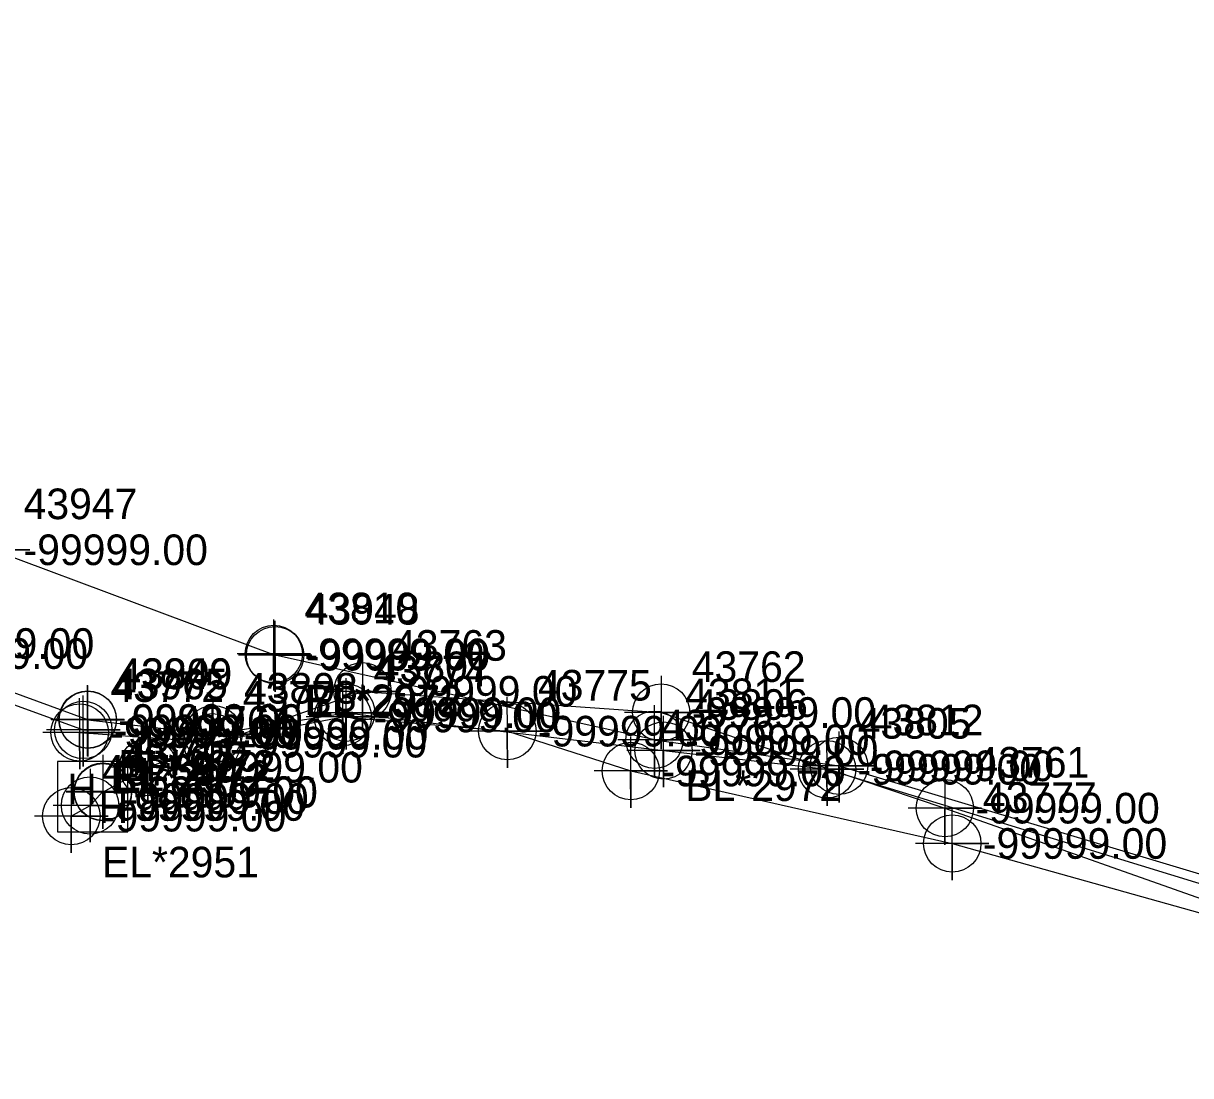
# Model space of a CAD drawing. Extents: x 2083698 to 2094313, y 743246 to 752873.
# Drawn here: x 2091439.4 to 2091534.7, y 747273.4 to 747359.3 of the extents above; entities that cross this region are included whole.
import ezdxf

# ---------------------------------------------------------------- set-up
doc = ezdxf.new("R2010")
doc.units = 0
for name, color, linetype in [('COGO Default Spiral', 7, 'Continuous'), ('Exist Other Culture Fence Line', 7, 'Continuous'), ('Exist Property Iron Pin Leader', 7, 'Continuous'), ('Exist Property Iron Pin Text', 7, 'Continuous'), ('Exist Property Monument Leader', 7, 'Continuous'), ('Exist Property Monument Text', 7, 'Continuous'), ('Exist Right of Way Line Leader', 7, 'Continuous'), ('Exist Right of Way Line Text', 7, 'Continuous'), ('Exist Utilities Power Joint Use Telephone Cogo Elevation', 7, 'Continuous'), ('Exist Utilities Power Joint Use Telephone Cogo Number', 7, 'Continuous'), ('Exist Utilities Power UG Cable SUE LOS B', 7, 'Continuous'), ('Exist Utilities Telephone UG Conduit SUE LOS B', 7, 'Continuous'), ('Scratch_Level_2', 7, 'Continuous'), ('Scratch_Level_3', 7, 'Continuous'), ('Scratch_Level_5', 7, 'Continuous')]:
    doc.layers.add(name, color=color, linetype=linetype)

msp = doc.modelspace()

# ---------------------------------------------------------------- linework, layer by layer
at = {"layer": 'COGO Default Spiral'}
msp.add_line((2091445.134, 747296.025), (2091445.134, 747296.025), dxfattribs=at)
msp.add_lwpolyline([(2091442.184, 747293.3), (2091447.934, 747293.3), (2091447.934, 747299.05), (2091442.184, 747299.05), (2091442.184, 747293.3)], dxfattribs=at)
at = {"layer": 'Exist Property Iron Pin Text'}
for points in [[(2091467.087, 747307.78), (2091467.087, 747301.78), (2091467.087, 747304.78), (2091470.087, 747304.78), (2091464.087, 747304.78)], [(2091491.485, 747306.049), (2091491.485, 747300.049), (2091491.485, 747303.049), (2091494.485, 747303.049), (2091488.485, 747303.049)], [(2091449.563, 747301.581), (2091449.563, 747295.581), (2091449.563, 747298.581), (2091452.563, 747298.581), (2091446.563, 747298.581)], [(2091445.88, 747299.588), (2091445.88, 747293.588), (2091445.88, 747296.588), (2091448.88, 747296.588), (2091442.88, 747296.588)], [(2091445.887, 747299.543), (2091445.887, 747293.543), (2091445.887, 747296.543), (2091448.887, 747296.543), (2091442.887, 747296.543)], [(2091444.836, 747298.46), (2091444.836, 747292.46), (2091444.836, 747295.46), (2091447.836, 747295.46), (2091441.836, 747295.46)], [(2091514.66, 747298.24), (2091514.66, 747292.24), (2091514.66, 747295.24), (2091517.66, 747295.24), (2091511.66, 747295.24)], [(2091443.305, 747297.587), (2091443.305, 747291.587), (2091443.305, 747294.587), (2091446.305, 747294.587), (2091440.305, 747294.587)]]:
    msp.add_lwpolyline(points, dxfattribs=at)
for centre in [(2091467.087, 747304.78), (2091491.485, 747303.049), (2091449.563, 747298.581), (2091445.88, 747296.588), (2091445.887, 747296.543), (2091444.836, 747295.46), (2091514.66, 747295.24), (2091443.305, 747294.587)]:
    msp.add_circle(centre, 2.344, dxfattribs=at)
at = {"layer": 'Exist Right of Way Line Text'}
for points in [[(2091436.874, 747319.158), (2091436.907, 747313.343), (2091436.89, 747316.343), (2091439.907, 747316.343), (2091433.907, 747316.343)], [(2091459.814, 747310.653), (2091459.847, 747304.838), (2091459.83, 747307.838), (2091462.847, 747307.838), (2091456.847, 747307.838)], [(2091459.918, 747310.548), (2091459.951, 747304.733), (2091459.934, 747307.733), (2091462.951, 747307.733), (2091456.951, 747307.733)], [(2091465.725, 747305.846), (2091465.758, 747300.031), (2091465.741, 747303.031), (2091468.758, 747303.031), (2091462.758, 747303.031)], [(2091444.601, 747305.295), (2091444.634, 747299.48), (2091444.617, 747302.48), (2091447.634, 747302.48), (2091441.634, 747302.48)], [(2091444.621, 747305.266), (2091444.654, 747299.451), (2091444.637, 747302.451), (2091447.654, 747302.451), (2091441.654, 747302.451)], [(2091465.448, 747305.502), (2091465.481, 747299.687), (2091465.464, 747302.687), (2091468.481, 747302.687), (2091462.481, 747302.687)], [(2091443.957, 747304.233), (2091443.99, 747298.418), (2091443.973, 747301.418), (2091446.99, 747301.418), (2091440.99, 747301.418)], [(2091444.251, 747304.444), (2091444.284, 747298.629), (2091444.267, 747301.629), (2091447.284, 747301.629), (2091441.284, 747301.629)], [(2091454.873, 747304.095), (2091454.906, 747298.28), (2091454.889, 747301.28), (2091457.906, 747301.28), (2091451.906, 747301.28)], [(2091478.888, 747304.344), (2091478.921, 747298.529), (2091478.904, 747301.529), (2091481.921, 747301.529), (2091475.921, 747301.529)], [(2091490.912, 747303.64), (2091490.945, 747297.825), (2091490.928, 747300.825), (2091493.945, 747300.825), (2091487.945, 747300.825)], [(2091454.781, 747303.444), (2091454.814, 747297.629), (2091454.797, 747300.629), (2091457.814, 747300.629), (2091451.814, 747300.629)], [(2091491.644, 747302.768), (2091491.677, 747296.953), (2091491.66, 747299.953), (2091494.677, 747299.953), (2091488.677, 747299.953)], [(2091488.975, 747301.09), (2091489.008, 747295.275), (2091488.991, 747298.275), (2091492.008, 747298.275), (2091486.008, 747298.275)], [(2091505.003, 747301.232), (2091505.036, 747295.417), (2091505.019, 747298.417), (2091508.036, 747298.417), (2091502.036, 747298.417)], [(2091505.986, 747301.511), (2091506.019, 747295.696), (2091506.002, 747298.696), (2091509.019, 747298.696), (2091503.019, 747298.696)], [(2091515.23, 747295.171), (2091515.263, 747289.356), (2091515.246, 747292.356), (2091518.263, 747292.356), (2091512.263, 747292.356)]]:
    msp.add_lwpolyline(points, dxfattribs=at)
for centre in [(2091459.847, 747307.838), (2091459.951, 747307.733), (2091444.634, 747302.48), (2091444.654, 747302.451), (2091465.481, 747302.687), (2091465.758, 747303.031), (2091443.99, 747301.418), (2091444.284, 747301.629), (2091454.906, 747301.28), (2091478.921, 747301.529), (2091454.814, 747300.629), (2091490.945, 747300.825), (2091491.677, 747299.953), (2091505.036, 747298.417), (2091506.019, 747298.696), (2091489.008, 747298.275), (2091515.263, 747292.356)]:
    msp.add_circle(centre, 2.344, dxfattribs=at)
at = {"layer": 'Exist Utilities Power UG Cable SUE LOS B'}
msp.add_lwpolyline([(2091443.305, 747294.587), (2091444.836, 747295.46), (2091445.88, 747296.588), (2091445.887, 747296.543), (2091449.563, 747298.581), (2091467.087, 747304.78), (2091491.485, 747303.049), (2091514.66, 747295.24), (2091539.78, 747286.368), (2091567.549, 747275.316), (2091580.787, 747271.093), (2091590.136, 747265.131), (2091610.579, 747257.092), (2091619.646, 747254.52), (2091635.772, 747249.044), (2091646.18, 747244.965), (2091658.315, 747240.329), (2091670.957, 747235.991)], dxfattribs=at)
at = {"layer": 'Exist Utilities Telephone UG Conduit SUE LOS B'}
msp.add_line((2091490.945, 747300.825), (2091459.951, 747307.733), dxfattribs=at)
for points in [[(2091335.853, 747359.338), (2091338.518, 747357.778), (2091345.13, 747354.058), (2091356.112, 747350.876), (2091369.7, 747346.742), (2091381.718, 747340.664), (2091412.833, 747327.222), (2091436.907, 747316.343), (2091459.951, 747307.733)], [(2091358.632, 747332.717), (2091362.096, 747333.547), (2091368.967, 747333.088), (2091377.912, 747329.056), (2091397.559, 747320.735), (2091413.319, 747315.153), (2091427.626, 747308.684), (2091444.634, 747302.48)], [(2091358.585, 747332.086), (2091362.083, 747332.803), (2091368.482, 747332.364), (2091377.074, 747328.149), (2091393.477, 747322.221), (2091396.325, 747319.978), (2091412.93, 747314.198), (2091427.112, 747307.865), (2091444.284, 747301.629)], [(2091443.99, 747301.418), (2091454.814, 747300.629), (2091465.481, 747302.687), (2091478.921, 747301.529), (2091489.008, 747298.275), (2091515.263, 747292.356), (2091541.6, 747284.977), (2091562.582, 747273.963), (2091581.391, 747270.013), (2091631.741, 747247.355), (2091657.75, 747234.801), (2091691.097, 747222.646), (2091708.023, 747218.162), (2091735.195, 747207.662), (2091760.392, 747198.48), (2091779.153, 747191.388), (2091790.081, 747187.606)], [(2091444.654, 747302.451), (2091454.906, 747301.28), (2091465.758, 747303.031), (2091491.677, 747299.953), (2091505.036, 747298.417), (2091539.924, 747287.737), (2091562.941, 747276.393), (2091581.172, 747271.237), (2091590.138, 747268.188), (2091609.855, 747260.547), (2091622.546, 747256.744), (2091630.833, 747249.508), (2091644.203, 747241.571), (2091657.272, 747236.193), (2091669.664, 747231.37), (2091690.193, 747224.674), (2091708.409, 747218.752), (2091733.869, 747209.292), (2091760.728, 747199.484), (2091779.903, 747191.767), (2091790.314, 747188.764)], [(2091490.945, 747300.825), (2091506.019, 747298.696), (2091541.096, 747288.194), (2091582.192, 747271.692), (2091589.995, 747269.174), (2091612.256, 747261.765), (2091622.877, 747257.298), (2091635.492, 747248.26), (2091645.181, 747242.908), (2091657.599, 747237.343), (2091669.804, 747231.917), (2091690.327, 747225.219), (2091708.507, 747219.396), (2091733.921, 747209.815), (2091760.792, 747200.302), (2091780.023, 747192.965), (2091790.517, 747189.379)]]:
    msp.add_lwpolyline(points, dxfattribs=at)

# ---------------------------------------------------------------- texts
at = {"layer": 'COGO Default Spiral'}
for p in [(2091442.975, 747295.551), (2091445.539, 747294.031)]:
    msp.add_text('H', height=2.5, dxfattribs=at).set_placement(p)
at = {"layer": 'Exist Other Culture Fence Line'}
msp.add_text('-99999.00', height=2.5, dxfattribs=at).set_placement((2091447.634, 747294.775))
at = {"layer": 'Exist Property Iron Pin Leader'}
for s, p in [('43763', (2091469.587, 747307.28)), ('43762', (2091493.985, 747305.549)), ('43764', (2091452.063, 747301.081)), ('43766', (2091448.38, 747299.088)), ('43765', (2091448.387, 747299.043)), ('43767', (2091447.336, 747297.96)), ('43761', (2091517.16, 747297.74)), ('43768', (2091445.805, 747297.087))]:
    msp.add_text(s, height=2.5, dxfattribs=at).set_placement(p)
at = {"layer": 'Exist Property Monument Leader'}
msp.add_text('EL*2951', height=2.5, dxfattribs=at).set_placement((2091445.805, 747289.587))
at = {"layer": 'Exist Property Monument Text'}
for p in [(2091469.587, 747303.53), (2091493.985, 747301.799), (2091452.063, 747297.331), (2091448.38, 747295.338), (2091448.387, 747295.293), (2091447.336, 747294.21), (2091517.16, 747293.99), (2091445.805, 747293.337)]:
    msp.add_text('-99999.00', height=2.5, dxfattribs=at).set_placement(p)
at = {"layer": 'Exist Right of Way Line Leader'}
for s, p in [('43947', (2091439.407, 747318.843)), ('43810', (2091462.347, 747310.338)), ('43948', (2091462.451, 747310.233)), ('43949', (2091447.134, 747304.98)), ('43809', (2091447.154, 747304.951)), ('43774', (2091467.981, 747305.187)), ('43807', (2091468.258, 747305.531)), ('43965', (2091446.784, 747304.129)), ('43775', (2091481.421, 747304.029)), ('43772', (2091446.49, 747303.918)), ('43773', (2091457.314, 747303.129)), ('43808', (2091457.406, 747303.78)), ('43811', (2091493.445, 747303.325)), ('43806', (2091494.177, 747302.453)), ('43812', (2091508.519, 747301.196)), ('43776', (2091491.508, 747300.775)), ('43805', (2091507.536, 747300.917)), ('43777', (2091517.763, 747294.856))]:
    msp.add_text(s, height=2.5, dxfattribs=at).set_placement(p)
at = {"layer": 'Exist Utilities Power Joint Use Telephone Cogo Elevation'}
msp.add_text('-99999.00', height=2.5, dxfattribs=at).set_placement((2091445.799, 747293.339))
at = {"layer": 'Exist Utilities Power Joint Use Telephone Cogo Number'}
msp.add_text('43769', height=2.5, dxfattribs=at).set_placement((2091445.799, 747297.089))
at = {"layer": 'Scratch_Level_2'}
for p in [(2091439.407, 747315.093), (2091430.126, 747307.434), (2091429.612, 747306.615), (2091462.347, 747306.588), (2091462.451, 747306.483), (2091447.134, 747301.23), (2091447.154, 747301.201), (2091467.981, 747301.437), (2091468.258, 747301.781), (2091446.49, 747300.168), (2091446.784, 747300.379), (2091481.421, 747300.279), (2091457.314, 747299.379), (2091457.406, 747300.03), (2091493.445, 747299.575), (2091494.177, 747298.703), (2091508.519, 747297.446), (2091491.508, 747297.025), (2091507.536, 747297.167), (2091517.763, 747291.106)]:
    msp.add_text('-99999.00', height=2.5, dxfattribs=at).set_placement(p)
at = {"layer": 'Scratch_Level_3'}
for s, p in [('BL*2972', (2091462.347, 747302.838)), ('EL*2972', (2091462.451, 747302.733)), ('BL*2972', (2091447.134, 747297.48)), ('EL*2972', (2091447.154, 747297.451)), ('BL*2972', (2091446.49, 747296.418)), ('EL*2972', (2091446.784, 747296.629)), ('BL*2972', (2091493.445, 747295.825))]:
    msp.add_text(s, height=2.5, dxfattribs=at).set_placement(p)
at = {"layer": 'Scratch_Level_5'}
msp.add_text('43771', height=2.5, dxfattribs=at).set_placement((2091447.634, 747298.525))

doc.saveas('drawing.dxf')
